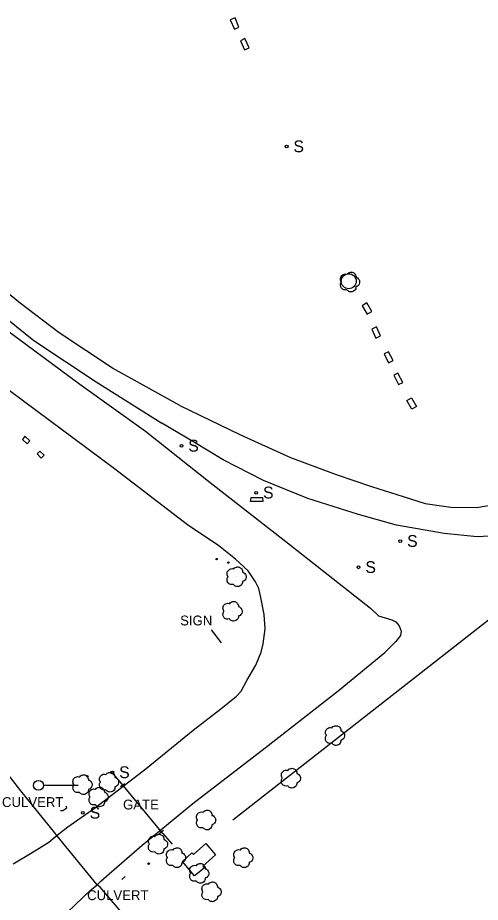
# Model space of a CAD drawing. Extents: x 368532 to 392481, y 10654822 to 10676899.
# Drawn here: x 371851.4 to 372086.5, y 10672290.3 to 10672739.7 of the extents above; entities that cross this region are included whole.
import ezdxf

# ---------------------------------------------------------------- set-up
doc = ezdxf.new("R2010")
doc.units = 0
for name, color, linetype in [('p_drainage culvert', 7, 'Continuous'), ('p_railroad rr control', 7, 'Continuous'), ('p_road - paved curb', 7, 'Continuous'), ('p_road conc barrier', 7, 'Continuous'), ('p_road dirt road', 7, 'Continuous'), ('p_structure building', 7, 'Continuous'), ('p_structure fence', 7, 'Continuous'), ('p_structure sign', 7, 'Continuous'), ('p_structure unidentified', 7, 'Continuous'), ('p_structure wall', 7, 'Continuous'), ('p_veg tree', 7, 'Continuous')]:
    doc.layers.add(name, color=color, linetype=linetype)

msp = doc.modelspace()

# ---------------------------------------------------------------- linework, layer by layer
at = {"layer": 'p_drainage culvert'}
for p, q in [((371873.2, 10672336.96), (371874.31, 10672336.9)), ((371874.31, 10672336.9), (371876.31, 10672338.32)), ((371876.31, 10672338.32), (371876.01, 10672339.2)), ((371904.39, 10672301.83), (371906.06, 10672303.34))]:
    msp.add_line(p, q, dxfattribs=at)
at = {"layer": 'p_railroad rr control'}
msp.add_line((371882.04, 10672349.69), (371864.46, 10672349.69), dxfattribs=at)
for points in [[(371893.28, 10672298.06), (371891.72, 10672299.1), (371871.28, 10672324.32), (371870.25, 10672325.58), (371852.93, 10672346.95), (371838.21, 10672365.75)], [(372098.64, 10672082.81), (372074.23, 10672105.89), (372049.35, 10672129.84), (372009.23, 10672170.36), (371976.54, 10672204.67), (371942.2, 10672241.75), (371904, 10672285.45), (371893.28, 10672298.06)]]:
    msp.add_lwpolyline(points, dxfattribs=at)
msp.add_circle((371861.96, 10672349.71), 2.52, dxfattribs=at)
at = {"layer": 'p_road - paved curb'}
for p, q in [((371834.46, 10672589.32), (371882.9, 10672553.59)), ((371899.93, 10672510.99), (371836.08, 10672558.31)), ((371882.9, 10672553.59), (371916.27, 10672529.67)), ((371916.27, 10672529.67), (371949.24, 10672503.49)), ((371937.74, 10672482.02), (371899.93, 10672510.99)), ((371949.24, 10672503.49), (371987.64, 10672473.52)), ((371953.62, 10672471.36), (371937.74, 10672482.02)), ((371962.09, 10672464.56), (371953.62, 10672471.36)), ((371987.64, 10672473.52), (372030.7, 10672439.8)), ((371968.46, 10672458.65), (371962.09, 10672464.56)), ((371972.25, 10672453.14), (371968.46, 10672458.65)), ((371974, 10672449.77), (371972.25, 10672453.14)), ((371974.96, 10672445.07), (371974, 10672449.77)), ((371976.7, 10672436.5), (371974.96, 10672445.07)), ((372030.7, 10672439.8), (372034.74, 10672435.86)), ((371977.12, 10672429.3), (371976.7, 10672436.5)), ((372034.74, 10672435.86), (372041.48, 10672433.86)), ((372041.48, 10672433.86), (372043.66, 10672432.75)), ((372043.66, 10672432.75), (372045.35, 10672430.67)), ((372045.35, 10672430.67), (372046.24, 10672427.97)), ((371976.16, 10672421.66), (371977.12, 10672429.3)), ((372045.9, 10672425.8), (372043.62, 10672422.73)), ((372046.24, 10672427.97), (372045.9, 10672425.8)), ((371975.09, 10672417.33), (371976.16, 10672421.66)), ((372043.62, 10672422.73), (372037.97, 10672417.21)), ((371972.36, 10672410.8), (371975.09, 10672417.33)), ((372014.33, 10672397.73), (372037.97, 10672417.21)), ((371967.93, 10672402.9), (371972.36, 10672410.8)), ((371964.95, 10672397.48), (371967.93, 10672402.9)), ((371954.62, 10672388.53), (371962.58, 10672395.03)), ((371962.58, 10672395.03), (371964.95, 10672397.48)), ((371977.16, 10672368.71), (372014.33, 10672397.73)), ((371940.59, 10672377.68), (371954.62, 10672388.53)), ((371916.65, 10672358.23), (371940.59, 10672377.68)), ((371940.47, 10672340.42), (371977.16, 10672368.71)), ((371890.88, 10672338.49), (371916.65, 10672358.23)), ((371914.62, 10672319.35), (371940.47, 10672340.42)), ((371876.94, 10672328.67), (371890.88, 10672338.49)), ((371873.19, 10672325.77), (371876.94, 10672328.67)), ((371867.13, 10672320.78), (371869.38, 10672322.75)), ((371869.38, 10672322.75), (371871.28, 10672324.32)), ((371871.28, 10672324.32), (371873.19, 10672325.77)), ((371858.66, 10672315.59), (371867.13, 10672320.78)), ((371897.91, 10672304.78), (371914.62, 10672319.35)), ((371849.16, 10672309.85), (371858.66, 10672315.59)), ((371893.66, 10672301.09), (371897.91, 10672304.78)), ((371891.72, 10672299.1), (371893.66, 10672301.09)), ((371872.95, 10672281.78), (371888.13, 10672296.1)), ((371888.13, 10672296.1), (371889.89, 10672297.69)), ((371889.89, 10672297.69), (371891.72, 10672299.1))]:
    msp.add_line(p, q, dxfattribs=at)
at = {"layer": 'p_road conc barrier'}
for p, q in [((371961.92, 10672739.68), (371959.44, 10672738.6)), ((371959.44, 10672738.6), (371961.53, 10672733.93)), ((371963.8, 10672734.91), (371961.92, 10672739.68)), ((371961.53, 10672733.93), (371963.8, 10672734.91)), ((371966.9, 10672729.04), (371964.58, 10672727.85)), ((371964.58, 10672727.85), (371966.72, 10672723.39)), ((371969.04, 10672724.42), (371966.9, 10672729.04)), ((371966.72, 10672723.39), (371969.04, 10672724.42)), ((372028.91, 10672594.78), (372026.44, 10672593.33)), ((372026.44, 10672593.33), (372028.99, 10672589.02)), ((372031.45, 10672590.47), (372028.91, 10672594.78)), ((372028.99, 10672589.02), (372031.45, 10672590.47)), ((372033.8, 10672582.61), (372031.32, 10672581.49)), ((372035.86, 10672578.06), (372033.8, 10672582.61)), ((372031.32, 10672581.49), (372033.38, 10672576.93)), ((372033.38, 10672576.93), (372035.86, 10672578.06)), ((372039.94, 10672570.02), (372037.65, 10672568.85)), ((372042.25, 10672565.53), (372039.94, 10672570.02)), ((372037.65, 10672568.85), (372039.95, 10672564.35)), ((372039.95, 10672564.35), (372042.25, 10672565.53)), ((372044.65, 10672559.14), (372042.58, 10672558.08)), ((372042.58, 10672558.08), (372045, 10672553.35)), ((372047.07, 10672554.4), (372044.65, 10672559.14)), ((372045, 10672553.35), (372047.07, 10672554.4)), ((372049.18, 10672545.2), (372051.62, 10672546.59)), ((372051.62, 10672546.59), (372054.13, 10672542.18)), ((372051.7, 10672540.79), (372049.18, 10672545.2)), ((372054.13, 10672542.18), (372051.7, 10672540.79)), ((371969.71, 10672493.96), (371970.01, 10672496.01)), ((371976.02, 10672493.99), (371969.71, 10672493.96)), ((371970.01, 10672496.01), (371975.88, 10672495.86)), ((371975.88, 10672495.86), (371976.02, 10672493.99))]:
    msp.add_line(p, q, dxfattribs=at)
at = {"layer": 'p_road dirt road'}
for p, q in [((371851.9, 10672595.09), (371824.35, 10672618.18)), ((371834.72, 10672595.78), (371859.55, 10672575.64)), ((371872.47, 10672579.64), (371851.9, 10672595.09)), ((371899.55, 10672561.72), (371872.47, 10672579.64)), ((371859.55, 10672575.64), (371891.29, 10672554.78)), ((371933.73, 10672542.67), (371899.55, 10672561.72)), ((371891.29, 10672554.78), (371924.61, 10672533.66)), ((371933.73, 10672542.67), (371964.31, 10672528)), ((371941.31, 10672523.84), (371924.61, 10672533.66)), ((371964.31, 10672528), (371990.08, 10672516.25)), ((371955.84, 10672515.1), (371941.31, 10672523.84)), ((371990.08, 10672516.25), (372013.29, 10672507.67)), ((371976.25, 10672504.66), (371955.84, 10672515.1)), ((372013.29, 10672507.67), (372031.29, 10672501.53)), ((371998.83, 10672495.51), (371976.25, 10672504.66)), ((372031.29, 10672501.53), (372047.34, 10672496.43)), ((372024.62, 10672487.36), (371998.83, 10672495.51)), ((372047.34, 10672496.43), (372058.55, 10672492.94)), ((372058.55, 10672492.94), (372071.52, 10672491.09)), ((372084.73, 10672490.89), (372095.64, 10672492.67)), ((372071.52, 10672491.09), (372084.73, 10672490.89)), ((372043.96, 10672481.93), (372024.62, 10672487.36)), ((372068.2, 10672477.73), (372043.96, 10672481.93)), ((372084.99, 10672475.96), (372068.2, 10672477.73)), ((372098.36, 10672476.69), (372084.99, 10672475.96))]:
    msp.add_line(p, q, dxfattribs=at)
at = {"layer": 'p_structure building'}
msp.add_lwpolyline([(371952.01, 10672314.48), (371945.46, 10672308.64), (371946.14, 10672307.72), (371941.34, 10672303.77), (371935.14, 10672311.05), (371939.91, 10672315.41), (371940.75, 10672314.65), (371946.94, 10672320.14)], close=True, dxfattribs=at)
at = {"layer": 'p_structure fence'}
for p, q in [((371904.26, 10672350.47), (371899.25, 10672356.34)), ((371903.59, 10672349.14), (371905.9, 10672350.71)), ((371925.14, 10672325.18), (371904.26, 10672350.47)), ((371923.16, 10672325.14), (371925.48, 10672327.01)), ((371925.14, 10672325.18), (371929.82, 10672319.82))]:
    msp.add_line(p, q, dxfattribs=at)
at = {"layer": 'p_structure sign'}
msp.add_lwpolyline([(371954.92, 10672422.18), (371949.91, 10672428.7)], dxfattribs=at)
for centre in [(371988.08, 10672674.23), (371934.61, 10672522.15), (371972.63, 10672498.35), (372045.87, 10672473.74), (372024.66, 10672460.5), (371899.49, 10672356.28), (371884.52, 10672335.72)]:
    msp.add_circle(centre, 0.713, dxfattribs=at)
at = {"layer": 'p_structure unidentified'}
for p, q in [((371855.09, 10672527.04), (371853.81, 10672525.44)), ((371853.81, 10672525.44), (371856.15, 10672523.17)), ((371857.51, 10672524.71), (371855.09, 10672527.04)), ((371856.15, 10672523.17), (371857.51, 10672524.71)), ((371861.2, 10672518.14), (371862.66, 10672519.52)), ((371863.31, 10672515.94), (371861.2, 10672518.14)), ((371862.66, 10672519.52), (371864.77, 10672517.38)), ((371864.77, 10672517.38), (371863.31, 10672515.94))]:
    msp.add_line(p, q, dxfattribs=at)
for centre, radius in [((372019.65, 10672605.81), 3.81), ((371952.46, 10672464.64), 0.375), ((371958.51, 10672462.9), 0.375), ((371886.78, 10672354.35), 0.375), ((371917.95, 10672309.9), 0.375)]:
    msp.add_circle(centre, radius, dxfattribs=at)
at = {"layer": 'p_structure wall'}
msp.add_line((371960.8, 10672332.25), (372103.45, 10672443.92), dxfattribs=at)
at = {"layer": 'p_veg tree'}
for p, q in [((372020.1, 10672605.42), (372020.1, 10672605.42)), ((371962.42, 10672455.71), (371962.42, 10672455.71)), ((371960.37, 10672438.18), (371960.37, 10672438.18)), ((372012.45, 10672375.06), (372012.45, 10672375.06)), ((371990.04, 10672353.4), (371990.04, 10672353.4)), ((371884.11, 10672350.09), (371884.11, 10672350.09)), ((371897.6, 10672351.37), (371897.6, 10672351.37)), ((371892.26, 10672343.84), (371892.26, 10672343.84)), ((371946.91, 10672332.14), (371946.91, 10672332.14)), ((371922.47, 10672319.87), (371922.47, 10672319.87)), ((371931.64, 10672312.98), (371931.64, 10672312.98)), ((371965.83, 10672312.98), (371965.83, 10672312.98)), ((371943.45, 10672305.05), (371943.45, 10672305.05)), ((371949.69, 10672295.68), (371949.69, 10672295.68))]:
    msp.add_line(p, q, dxfattribs=at)
for points in [[(372018.75, 10672601.48), (372017.19, 10672601.44), (372015.88, 10672602.38), (372015.47, 10672603.83), (372015.55, 10672604.68), (372015.88, 10672605.3), (372015.98, 10672605.41), (372015.92, 10672605.5), (372015.52, 10672606.37), (372015.81, 10672608.28), (372017.37, 10672609.4), (372018.67, 10672609.35), (372018.81, 10672609.31), (372018.88, 10672609.41), (372019.83, 10672610.17), (372021.44, 10672610.33), (372022.82, 10672609.4), (372023.27, 10672608.41), (372023.35, 10672607.86), (372023.33, 10672607.75), (372023.44, 10672607.76), (372024.05, 10672607.47), (372024.91, 10672606.53), (372025.18, 10672604.98), (372024.58, 10672603.72), (372023.64, 10672603.08), (372023.39, 10672603.01), (372023.34, 10672602.96), (372023.33, 10672602.89), (372023.29, 10672602.44), (372022.98, 10672601.52), (372022.06, 10672600.72), (372020.85, 10672600.37), (372019.33, 10672600.88), (372018.73, 10672601.49)], [(371961.07, 10672451.77), (371959.52, 10672451.73), (371958.21, 10672452.67), (371957.79, 10672454.12), (371957.88, 10672454.96), (371958.21, 10672455.58), (371958.31, 10672455.7), (371958.24, 10672455.79), (371957.84, 10672456.66), (371958.13, 10672458.57), (371959.69, 10672459.69), (371960.99, 10672459.64), (371961.13, 10672459.59), (371961.2, 10672459.69), (371962.15, 10672460.45), (371963.76, 10672460.62), (371965.15, 10672459.69), (371965.6, 10672458.7), (371965.67, 10672458.15), (371965.66, 10672458.04), (371965.76, 10672458.05), (371966.37, 10672457.76), (371967.23, 10672456.82), (371967.5, 10672455.27), (371966.9, 10672454.01), (371965.97, 10672453.36), (371965.71, 10672453.29), (371965.66, 10672453.25), (371965.65, 10672453.18), (371965.61, 10672452.73), (371965.3, 10672451.8), (371964.39, 10672451.01), (371963.18, 10672450.65), (371961.66, 10672451.16), (371961.05, 10672451.77)], [(371959.02, 10672434.24), (371957.46, 10672434.21), (371956.15, 10672435.15), (371955.74, 10672436.59), (371955.82, 10672437.44), (371956.15, 10672438.06), (371956.25, 10672438.17), (371956.19, 10672438.27), (371955.79, 10672439.14), (371956.08, 10672441.04), (371957.64, 10672442.16), (371958.94, 10672442.11), (371959.08, 10672442.07), (371959.15, 10672442.17), (371960.1, 10672442.93), (371961.71, 10672443.1), (371963.09, 10672442.16), (371963.54, 10672441.17), (371963.62, 10672440.63), (371963.6, 10672440.52), (371963.71, 10672440.52), (371964.32, 10672440.24), (371965.18, 10672439.29), (371965.45, 10672437.74), (371964.85, 10672436.49), (371963.91, 10672435.84), (371963.66, 10672435.77), (371963.61, 10672435.72), (371963.6, 10672435.66), (371963.56, 10672435.2), (371963.25, 10672434.28), (371962.33, 10672433.49), (371961.12, 10672433.13), (371959.6, 10672433.64), (371959, 10672434.25)], [(372011.1, 10672371.13), (372009.54, 10672371.09), (372008.23, 10672372.03), (372007.82, 10672373.47), (372007.9, 10672374.32), (372008.23, 10672374.94), (372008.33, 10672375.06), (372008.27, 10672375.15), (372007.87, 10672376.02), (372008.16, 10672377.93), (372009.72, 10672379.04), (372011.02, 10672379), (372011.16, 10672378.95), (372011.23, 10672379.05), (372012.18, 10672379.81), (372013.79, 10672379.98), (372015.17, 10672379.05), (372015.62, 10672378.06), (372015.7, 10672377.51), (372015.68, 10672377.4), (372015.79, 10672377.4), (372016.4, 10672377.12), (372017.26, 10672376.17), (372017.53, 10672374.62), (372016.93, 10672373.37), (372015.99, 10672372.72), (372015.74, 10672372.65), (372015.69, 10672372.6), (372015.68, 10672372.54), (372015.64, 10672372.09), (372015.33, 10672371.16), (372014.41, 10672370.37), (372013.2, 10672370.01), (372011.68, 10672370.52), (372011.08, 10672371.13)], [(371988.69, 10672349.46), (371987.14, 10672349.43), (371985.83, 10672350.37), (371985.41, 10672351.81), (371985.5, 10672352.66), (371985.82, 10672353.28), (371985.92, 10672353.39), (371985.86, 10672353.49), (371985.46, 10672354.36), (371985.75, 10672356.27), (371987.31, 10672357.38), (371988.61, 10672357.33), (371988.75, 10672357.29), (371988.82, 10672357.39), (371989.77, 10672358.15), (371991.38, 10672358.32), (371992.77, 10672357.39), (371993.21, 10672356.39), (371993.29, 10672355.85), (371993.27, 10672355.74), (371993.38, 10672355.74), (371993.99, 10672355.46), (371994.85, 10672354.51), (371995.12, 10672352.96), (371994.52, 10672351.71), (371993.59, 10672351.06), (371993.33, 10672350.99), (371993.28, 10672350.94), (371993.27, 10672350.88), (371993.23, 10672350.43), (371992.92, 10672349.5), (371992, 10672348.71), (371990.79, 10672348.35), (371989.28, 10672348.86), (371988.67, 10672349.47)], [(371882.76, 10672346.15), (371881.21, 10672346.12), (371879.9, 10672347.06), (371879.48, 10672348.5), (371879.57, 10672349.35), (371879.89, 10672349.97), (371879.99, 10672350.08), (371879.93, 10672350.18), (371879.53, 10672351.05), (371879.82, 10672352.96), (371881.38, 10672354.07), (371882.68, 10672354.02), (371882.82, 10672353.98), (371882.89, 10672354.08), (371883.84, 10672354.84), (371885.45, 10672355.01), (371886.84, 10672354.08), (371887.28, 10672353.08), (371887.36, 10672352.54), (371887.34, 10672352.43), (371887.45, 10672352.43), (371888.06, 10672352.15), (371888.92, 10672351.2), (371889.19, 10672349.65), (371888.59, 10672348.4), (371887.66, 10672347.75), (371887.4, 10672347.68), (371887.35, 10672347.63), (371887.34, 10672347.57), (371887.3, 10672347.12), (371886.99, 10672346.19), (371886.07, 10672345.4), (371884.86, 10672345.04), (371883.35, 10672345.55), (371882.74, 10672346.16)], [(371896.25, 10672347.43), (371894.69, 10672347.4), (371893.38, 10672348.34), (371892.96, 10672349.78), (371893.05, 10672350.63), (371893.38, 10672351.25), (371893.48, 10672351.36), (371893.42, 10672351.45), (371893.02, 10672352.32), (371893.31, 10672354.23), (371894.86, 10672355.35), (371896.16, 10672355.3), (371896.31, 10672355.26), (371896.38, 10672355.36), (371897.33, 10672356.12), (371898.93, 10672356.29), (371900.32, 10672355.35), (371900.77, 10672354.36), (371900.85, 10672353.82), (371900.83, 10672353.7), (371900.94, 10672353.71), (371901.54, 10672353.42), (371902.41, 10672352.48), (371902.68, 10672350.93), (371902.08, 10672349.67), (371901.14, 10672349.03), (371900.89, 10672348.96), (371900.84, 10672348.91), (371900.83, 10672348.85), (371900.79, 10672348.39), (371900.48, 10672347.47), (371899.56, 10672346.67), (371898.35, 10672346.32), (371896.83, 10672346.83), (371896.23, 10672347.44)], [(371890.92, 10672339.9), (371889.36, 10672339.87), (371888.05, 10672340.81), (371887.63, 10672342.25), (371887.72, 10672343.1), (371888.05, 10672343.72), (371888.15, 10672343.83), (371888.08, 10672343.93), (371887.69, 10672344.8), (371887.98, 10672346.71), (371889.53, 10672347.82), (371890.83, 10672347.77), (371890.97, 10672347.73), (371891.04, 10672347.83), (371892, 10672348.59), (371893.6, 10672348.76), (371894.99, 10672347.83), (371895.44, 10672346.83), (371895.51, 10672346.29), (371895.5, 10672346.18), (371895.6, 10672346.18), (371896.21, 10672345.9), (371897.08, 10672344.95), (371897.35, 10672343.4), (371896.75, 10672342.15), (371895.81, 10672341.5), (371895.55, 10672341.43), (371895.5, 10672341.38), (371895.5, 10672341.32), (371895.45, 10672340.87), (371895.14, 10672339.94), (371894.23, 10672339.15), (371893.02, 10672338.79), (371891.5, 10672339.3), (371890.89, 10672339.91)], [(371945.56, 10672328.2), (371944.01, 10672328.17), (371942.7, 10672329.11), (371942.28, 10672330.55), (371942.37, 10672331.4), (371942.7, 10672332.02), (371942.8, 10672332.13), (371942.73, 10672332.23), (371942.33, 10672333.1), (371942.63, 10672335.01), (371944.18, 10672336.12), (371945.48, 10672336.07), (371945.62, 10672336.03), (371945.69, 10672336.13), (371946.64, 10672336.89), (371948.25, 10672337.06), (371949.64, 10672336.13), (371950.09, 10672335.13), (371950.16, 10672334.59), (371950.15, 10672334.48), (371950.25, 10672334.48), (371950.86, 10672334.2), (371951.72, 10672333.25), (371951.99, 10672331.7), (371951.39, 10672330.45), (371950.46, 10672329.8), (371950.2, 10672329.73), (371950.15, 10672329.68), (371950.15, 10672329.62), (371950.1, 10672329.17), (371949.79, 10672328.24), (371948.88, 10672327.45), (371947.67, 10672327.09), (371946.15, 10672327.6), (371945.54, 10672328.21)], [(371921.13, 10672315.93), (371919.57, 10672315.9), (371918.26, 10672316.84), (371917.84, 10672318.28), (371917.93, 10672319.13), (371918.26, 10672319.75), (371918.36, 10672319.86), (371918.29, 10672319.96), (371917.9, 10672320.83), (371918.19, 10672322.74), (371919.74, 10672323.85), (371921.04, 10672323.8), (371921.18, 10672323.76), (371921.25, 10672323.86), (371922.2, 10672324.62), (371923.81, 10672324.79), (371925.2, 10672323.86), (371925.65, 10672322.86), (371925.72, 10672322.32), (371925.71, 10672322.21), (371925.81, 10672322.21), (371926.42, 10672321.93), (371927.29, 10672320.98), (371927.55, 10672319.43), (371926.96, 10672318.18), (371926.02, 10672317.53), (371925.76, 10672317.46), (371925.71, 10672317.41), (371925.71, 10672317.35), (371925.66, 10672316.9), (371925.35, 10672315.97), (371924.44, 10672315.18), (371923.23, 10672314.82), (371921.71, 10672315.33), (371921.1, 10672315.94)], [(371930.29, 10672309.04), (371928.74, 10672309.01), (371927.43, 10672309.95), (371927.01, 10672311.39), (371927.1, 10672312.24), (371927.42, 10672312.86), (371927.52, 10672312.97), (371927.46, 10672313.07), (371927.06, 10672313.94), (371927.35, 10672315.84), (371928.91, 10672316.96), (371930.21, 10672316.91), (371930.35, 10672316.87), (371930.42, 10672316.97), (371931.37, 10672317.73), (371932.98, 10672317.9), (371934.37, 10672316.97), (371934.81, 10672315.97), (371934.89, 10672315.43), (371934.87, 10672315.32), (371934.98, 10672315.32), (371935.59, 10672315.04), (371936.45, 10672314.09), (371936.72, 10672312.54), (371936.12, 10672311.29), (371935.19, 10672310.64), (371934.93, 10672310.57), (371934.88, 10672310.52), (371934.87, 10672310.46), (371934.83, 10672310), (371934.52, 10672309.08), (371933.6, 10672308.29), (371932.39, 10672307.93), (371930.88, 10672308.44), (371930.27, 10672309.05)], [(371964.48, 10672309.04), (371962.93, 10672309.01), (371961.62, 10672309.95), (371961.2, 10672311.39), (371961.29, 10672312.24), (371961.61, 10672312.86), (371961.71, 10672312.98), (371961.65, 10672313.07), (371961.25, 10672313.94), (371961.54, 10672315.85), (371963.1, 10672316.96), (371964.4, 10672316.92), (371964.54, 10672316.87), (371964.61, 10672316.97), (371965.56, 10672317.73), (371967.17, 10672317.9), (371968.56, 10672316.97), (371969, 10672315.98), (371969.08, 10672315.43), (371969.07, 10672315.32), (371969.17, 10672315.32), (371969.78, 10672315.04), (371970.64, 10672314.09), (371970.91, 10672312.54), (371970.31, 10672311.29), (371969.38, 10672310.64), (371969.12, 10672310.57), (371969.07, 10672310.52), (371969.06, 10672310.46), (371969.02, 10672310.01), (371968.71, 10672309.08), (371967.8, 10672308.29), (371966.58, 10672307.93), (371965.07, 10672308.44), (371964.46, 10672309.05)], [(371942.1, 10672301.11), (371940.54, 10672301.08), (371939.23, 10672302.02), (371938.82, 10672303.46), (371938.9, 10672304.31), (371939.23, 10672304.93), (371939.33, 10672305.04), (371939.27, 10672305.14), (371938.87, 10672306.01), (371939.16, 10672307.92), (371940.71, 10672309.03), (371942.02, 10672308.98), (371942.16, 10672308.94), (371942.23, 10672309.04), (371943.18, 10672309.8), (371944.79, 10672309.97), (371946.17, 10672309.04), (371946.62, 10672308.04), (371946.7, 10672307.5), (371946.68, 10672307.39), (371946.79, 10672307.39), (371947.4, 10672307.11), (371948.26, 10672306.16), (371948.53, 10672304.61), (371947.93, 10672303.36), (371946.99, 10672302.71), (371946.74, 10672302.64), (371946.69, 10672302.59), (371946.68, 10672302.53), (371946.64, 10672302.08), (371946.33, 10672301.15), (371945.41, 10672300.36), (371944.2, 10672300), (371942.68, 10672300.51), (371942.08, 10672301.12)], [(371948.34, 10672291.74), (371946.78, 10672291.71), (371945.47, 10672292.65), (371945.06, 10672294.09), (371945.15, 10672294.94), (371945.47, 10672295.56), (371945.57, 10672295.67), (371945.51, 10672295.76), (371945.11, 10672296.64), (371945.4, 10672298.54), (371946.96, 10672299.66), (371948.26, 10672299.61), (371948.4, 10672299.57), (371948.47, 10672299.67), (371949.42, 10672300.43), (371951.03, 10672300.6), (371952.41, 10672299.66), (371952.86, 10672298.67), (371952.94, 10672298.13), (371952.92, 10672298.01), (371953.03, 10672298.02), (371953.64, 10672297.73), (371954.5, 10672296.79), (371954.77, 10672295.24), (371954.17, 10672293.98), (371953.23, 10672293.34), (371952.98, 10672293.27), (371952.93, 10672293.22), (371952.92, 10672293.16), (371952.88, 10672292.7), (371952.57, 10672291.78), (371951.65, 10672290.98), (371950.44, 10672290.63), (371948.92, 10672291.14), (371948.32, 10672291.75)]]:
    msp.add_spline(points, degree=3, dxfattribs=at)

# ---------------------------------------------------------------- texts
at = {"layer": 'p_drainage culvert'}
for p in [(371841.55, 10672338.72), (371884.81, 10672291.41)]:
    msp.add_text(' CULVERT', height=5, dxfattribs=at).set_placement(p)
at = {"layer": 'p_structure fence'}
msp.add_text(' GATE', height=5, dxfattribs=at).set_placement((371903.09, 10672337.47))
at = {"layer": 'p_structure sign'}
for s, height, p in [('S', 6, (371991.54, 10672671.34)), ('S', 6, (371938.07, 10672519.26)), ('S', 6, (371976.09, 10672495.46)), ('S', 6, (372049.33, 10672470.85)), ('S', 6, (372028.12, 10672457.6)), (' SIGN', 5, (371932.1, 10672430.97)), ('S', 6, (371902.95, 10672353.38)), ('S', 6, (371887.98, 10672332.82))]:
    msp.add_text(s, height=height, dxfattribs=at).set_placement(p)

doc.saveas('drawing.dxf')
